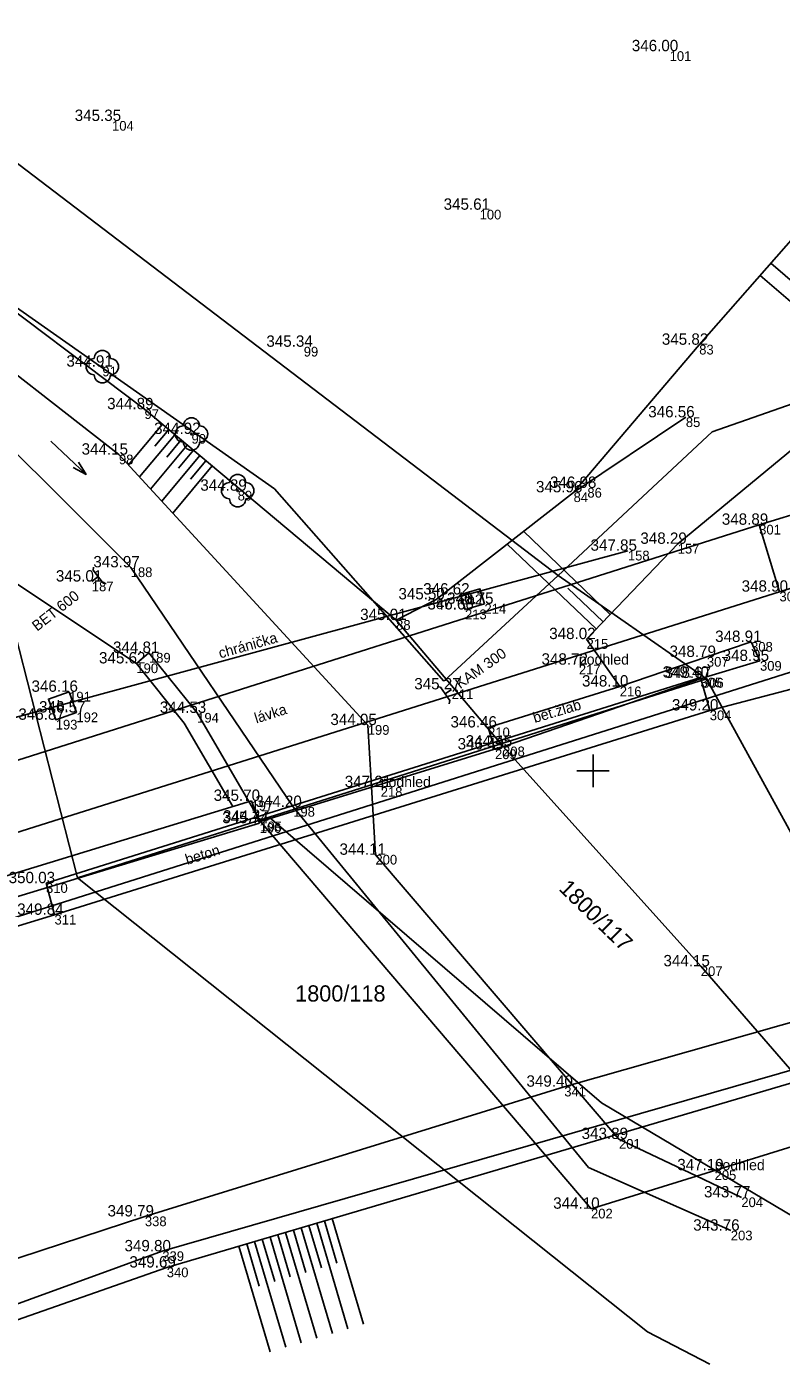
# Model space of a CAD drawing. Extents: x -614046 to -613877, y -1156755 to -1156623.
# Drawn here: x -613953.98 to -613935.35, y -1156734.51 to -1156701.64 of the extents above; entities that cross this region are included whole.
import ezdxf

# ---------------------------------------------------------------- set-up
doc = ezdxf.new("R2010")
doc.units = 0
for name, color, linetype in [('1-bod', 7, 'Continuous'), ('10-silnice', 7, 'Continuous'), ('11-zpevněné plochy', 7, 'Continuous'), ('14-terénní hrany', 7, 'Continuous'), ('15-šrafy', 7, 'Continuous'), ('16-vodní tok', 7, 'Continuous'), ('2-bod výška', 7, 'Continuous'), ('22-stromy', 7, 'Continuous'), ('27-kanalizace značky', 7, 'Continuous'), ('3-bod číslo', 7, 'Continuous'), ('40-popisy povrchů', 7, 'Continuous'), ('45-popis vodní tok', 7, 'Continuous'), ('50-hranice parcel KN', 7, 'Continuous'), ('61-hektarová síť', 7, 'Continuous'), ('7-plot', 7, 'Continuous'), ('9-zábradlí svodidlo', 7, 'Continuous')]:
    doc.layers.add(name, color=color, linetype=linetype)

# ---------------------------------------------------------------- blocks, each defined once
blk = doc.blocks.new('3.13_1')
at = {"layer": '22-stromy'}
blk.add_circle((0, 0), 0.05, dxfattribs=at)
for centre, start, end in [((0, 0.5), 0, 180), ((-0.5, 0), 90, 270), ((0.5, 0), 270, 90), ((0, -0.5), 180, 0)]:
    blk.add_arc(centre, 0.5, start, end, dxfattribs=at)
blk = doc.blocks.new('8.02')
at = {"layer": '45-popis vodní tok'}
blk.add_line((-3, 0), (0, 0), dxfattribs=at)
blk.add_lwpolyline([(-0.876, 0.23), (0, 0), (-0.876, -0.23)], dxfattribs=at)
blk = doc.blocks.new('VT')
at = {"layer": '27-kanalizace značky'}
for p, q in [((-0.629, 0.641), (-0.488, 0.5)), ((-0.488, -0.5), (-0.488, 0.5)), ((-0.488, 0), (0, 0)), ((-0.629, -0.641), (-0.488, -0.5))]:
    blk.add_line(p, q, dxfattribs=at)
blk = doc.blocks.new('POINT_DISPLAY')
blk.add_line((0, 0), (0, 0))

msp = doc.modelspace()

# ---------------------------------------------------------------- linework, layer by layer
at = {"layer": '10-silnice'}
msp.add_line((-613937.12, -1156718.51), (-613953.29, -1156723.55), dxfattribs=at)
for points in [[(-613937.12, -1156718.51), (-613933.57, -1156717.58), (-613925.62, -1156715.79), (-613924.84, -1156714.33), (-613924.32, -1156712.22), (-613924.87, -1156710.22), (-613924.77, -1156707.77), (-613925.4, -1156704.88), (-613927.05, -1156701.37), (-613930.42, -1156695.41), (-613933.78, -1156689.64), (-613939.48, -1156680.87), (-613941.35, -1156679.26), (-613943.8, -1156674.41), (-613943.3, -1156673.71), (-613943.36, -1156673.41), (-613946.37, -1156666.81), (-613948.28, -1156662.1), (-613952.52, -1156653.05)], [(-614040.86, -1156670.12), (-614026.04, -1156676.19), (-614020.49, -1156678.89), (-614017.81, -1156680.62), (-614014.97, -1156682.84), (-614010.02, -1156687.67), (-614005.03, -1156692.4), (-614001.46, -1156696.62), (-613996.56, -1156702.86), (-613991.22, -1156709.86), (-613982.03, -1156721.02), (-613980.56, -1156722.02), (-613978.09, -1156724.42), (-613976.34, -1156726.49), (-613975.01, -1156727.5), (-613973.5, -1156728.21), (-613971.99, -1156728.45), (-613970.47, -1156728.44), (-613968.47, -1156728.24), (-613968.3, -1156728.73), (-613958.25, -1156725.06), (-613953.29, -1156723.55)], [(-613903.37, -1156719.95), (-613913.49, -1156721.34), (-613924.71, -1156723.64), (-613933.07, -1156725.62), (-613940.71, -1156727.79), (-613951.06, -1156730.99), (-613956.76, -1156732.86), (-613974.57, -1156738.23), (-613984.2, -1156741.44), (-613994.97, -1156744.83), (-613999.58, -1156745.99)]]:
    msp.add_lwpolyline(points, dxfattribs=at)
at = {"layer": '11-zpevněné plochy'}
for p, q in [((-613935.9, -1156713.93), (-613926.56, -1156711.05)), ((-613935.4, -1156715.58), (-613925.97, -1156712.68)), ((-613959.11, -1156721.29), (-613935.9, -1156713.93)), ((-613935.9, -1156713.93), (-613935.4, -1156715.58)), ((-613956.51, -1156719.29), (-613939.14, -1156714.57)), ((-613958.54, -1156722.88), (-613935.4, -1156715.58)), ((-613937.19, -1156717.19), (-613936.1, -1156716.82)), ((-613936.1, -1156716.82), (-613935.88, -1156717.29)), ((-613939.34, -1156717.92), (-613937.19, -1156717.19)), ((-613935.88, -1156717.29), (-613937.31, -1156717.71)), ((-613953.5, -1156722.77), (-613937.35, -1156717.7)), ((-613937.31, -1156717.71), (-613942.42, -1156719.47)), ((-613937.35, -1156717.7), (-613937.12, -1156718.51)), ((-613942.59, -1156718.93), (-613939.34, -1156717.92)), ((-613942.42, -1156719.47), (-613942.59, -1156718.93)), ((-613942.22, -1156719.4), (-613948.21, -1156721.25)), ((-613937.34, -1156724.82), (-613942.22, -1156719.4)), ((-613954.8, -1156722.69), (-613948.43, -1156720.74)), ((-613948.43, -1156720.74), (-613948.23, -1156721.29)), ((-613948.23, -1156721.29), (-613954.64, -1156723.23)), ((-613948.21, -1156721.25), (-613940.05, -1156730.8)), ((-613953.29, -1156723.55), (-613953.5, -1156722.77)), ((-613933.83, -1156728.87), (-613937.34, -1156724.82)), ((-613940.05, -1156730.8), (-613933.83, -1156728.87))]:
    msp.add_line(p, q, dxfattribs=at)
for points in [[(-613942.68, -1156715.88), (-613943.16, -1156716.02), (-613943.27, -1156715.65), (-613942.79, -1156715.51)], [(-613952.93, -1156718.05), (-613952.75, -1156718.56), (-613953.26, -1156718.74), (-613953.44, -1156718.23)]]:
    msp.add_lwpolyline(points, close=True, dxfattribs=at)
at = {"layer": '14-terénní hrany'}
for p, q in [((-613959.65, -1156711.78), (-613951.27, -1156717.35)), ((-613940.16, -1156716.75), (-613939.34, -1156717.92))]:
    msp.add_line(p, q, dxfattribs=at)
for points in [[(-613997.04, -1156660.09), (-613993.56, -1156668.05), (-613988.66, -1156677.73), (-613984.98, -1156684.14), (-613979.93, -1156688.52), (-613976.6, -1156692.93), (-613968.24, -1156698.72), (-613963.28, -1156701.99), (-613959.08, -1156705.39), (-613955.46, -1156707.77), (-613951.07, -1156711.08), (-613944.86, -1156716.28)], [(-613940.16, -1156716.75), (-613937.91, -1156714.4), (-613933.94, -1156711.13), (-613930, -1156706.58), (-613928.58, -1156705.01), (-613927.95, -1156702.75), (-613928.18, -1156700.53), (-613933.55, -1156692.05), (-613939.5, -1156686.1), (-613943.86, -1156682.78), (-613948.89, -1156677.3), (-613953.73, -1156674.72)], [(-613951.83, -1156677.12), (-613952.88, -1156678.6), (-613948.44, -1156684.71), (-613942.44, -1156689.03), (-613937.52, -1156693.96), (-613931.49, -1156703.13), (-613933.8, -1156705.42), (-613937.38, -1156709.49), (-613940.48, -1156713.13)], [(-613958.96, -1156738.51), (-613958.16, -1156736.27), (-613957.15, -1156734.85), (-613955.67, -1156734.05), (-613950.52, -1156732.25), (-613932.98, -1156727.07), (-613924.59, -1156724.84)]]:
    msp.add_lwpolyline(points, dxfattribs=at)
at = {"layer": '15-šrafy'}
for p, q in [((-613932.848, -1156709.869), (-613935.61, -1156707.477)), ((-613933.11, -1156710.171), (-613935.874, -1156707.778)), ((-613950.626, -1156711.452), (-613951.466, -1156712.454)), ((-613950.32, -1156711.708), (-613951.193, -1156712.751)), ((-613950.473, -1156711.58), (-613950.816, -1156711.989)), ((-613950.013, -1156711.965), (-613950.92, -1156713.048)), ((-613950.166, -1156711.837), (-613950.522, -1156712.262)), ((-613949.86, -1156712.094), (-613950.229, -1156712.535)), ((-613949.706, -1156712.222), (-613950.646, -1156713.345)), ((-613949.553, -1156712.35), (-613949.936, -1156712.807)), ((-613949.4, -1156712.479), (-613950.373, -1156713.641)), ((-613939.58, -1156716.14), (-613941.72, -1156714.09)), ((-613939.92, -1156716.5), (-613942.12, -1156714.41)), ((-613939.75, -1156716.32), (-613940.62, -1156715.49)), ((-613946.82, -1156731.157), (-613946.05, -1156733.764)), ((-613946.628, -1156731.101), (-613946.32, -1156732.143)), ((-613946.436, -1156731.044), (-613945.666, -1156733.651)), ((-613947.97, -1156731.497), (-613947.201, -1156734.104)), ((-613947.779, -1156731.44), (-613947.471, -1156732.483)), ((-613947.587, -1156731.384), (-613946.817, -1156733.991)), ((-613947.395, -1156731.327), (-613947.087, -1156732.37)), ((-613947.203, -1156731.27), (-613946.433, -1156733.877)), ((-613947.011, -1156731.214), (-613946.703, -1156732.257)), ((-613948.738, -1156731.724), (-613947.968, -1156734.331)), ((-613948.546, -1156731.667), (-613948.238, -1156732.71)), ((-613948.354, -1156731.61), (-613947.584, -1156734.217)), ((-613948.162, -1156731.554), (-613947.854, -1156732.596))]:
    msp.add_line(p, q, dxfattribs=at)
at = {"layer": '16-vodní tok'}
for points in [[(-614001.52, -1156651.1), (-613998.11, -1156660.56), (-613996.01, -1156668.21), (-613990.4, -1156679.18), (-613986.72, -1156685.51), (-613977.75, -1156695.09), (-613969.35, -1156700.93), (-613963.95, -1156705.16), (-613955.95, -1156708.89), (-613951.7, -1156712.2), (-613945.56, -1156718.87), (-613945.478, -1156720.252)], [(-613947.4, -1156720.89), (-613951.41, -1156714.98), (-613956.19, -1156710.22), (-613963.8, -1156706.47), (-613969.59, -1156701.81), (-613978.15, -1156696.55), (-613986.41, -1156688.9), (-613987.27, -1156689.02), (-613988.53, -1156686.84), (-613992.1, -1156680.8), (-613997.89, -1156668.2), (-613999.34, -1156662.5), (-614003.52, -1156652.97)], [(-613945.478, -1156720.252), (-613945.37, -1156722.07), (-613939.36, -1156729.08), (-613937.452, -1156729.99)], [(-613938.735, -1156730.391), (-613940.11, -1156729.78), (-613947.4, -1156720.89)], [(-613937.452, -1156729.99), (-613936.34, -1156730.52)], [(-613936.6, -1156731.34), (-613938.735, -1156730.391)]]:
    msp.add_lwpolyline(points, dxfattribs=at)
at = {"layer": '50-hranice parcel KN'}
for points in [[(-613943.81, -1156712.94), (-613974.5, -1156689.56)], [(-613947.86, -1156713.04), (-613979.96, -1156690.49)], [(-613934.38, -1156710.7), (-613937.06, -1156711.64)], [(-613937.06, -1156711.64), (-613940.86, -1156715.18)], [(-613943.68, -1156717.79), (-613947.86, -1156713.04)], [(-613940.86, -1156715.18), (-613943.81, -1156712.94)], [(-613952.72, -1156722.64), (-613954.79, -1156714.58)], [(-613940.86, -1156715.18), (-613943.68, -1156717.79)], [(-613940.86, -1156715.18), (-613937.2, -1156717.73)], [(-613937.2, -1156717.73), (-613947.99, -1156721.14)], [(-613931.18, -1156728.7), (-613937.2, -1156717.73)], [(-613947.99, -1156721.14), (-613952.72, -1156722.64)], [(-613939.79, -1156728.19), (-613947.99, -1156721.14)], [(-613952.72, -1156722.64), (-613938.66, -1156733.84)], [(-613930.501, -1156733.694), (-613939.79, -1156728.19)], [(-613938.66, -1156733.84), (-613937.118, -1156734.635)]]:
    msp.add_lwpolyline(points, dxfattribs=at)
at = {"layer": '61-hektarová síť'}
for points in [[(-613940, -1156720.4), (-613940, -1156720), (-613940, -1156719.6)], [(-613940.4, -1156720), (-613940, -1156720), (-613939.6, -1156720)]]:
    msp.add_lwpolyline(points, dxfattribs=at)
at = {"layer": '7-plot'}
for p, q in [((-613940.48, -1156713.13), (-613937.71, -1156711.28)), ((-613943.87, -1156715.77), (-613940.48, -1156713.13)), ((-613944.86, -1156716.28), (-613943.87, -1156715.77)), ((-613942.22, -1156719.4), (-613944.86, -1156716.28)), ((-613951.27, -1156717.35), (-613950.09, -1156718.82)), ((-613949.77, -1156718.57), (-613948.21, -1156721.25)), ((-613950.09, -1156718.82), (-613948.89, -1156720.88))]:
    msp.add_line(p, q, dxfattribs=at)
msp.add_lwpolyline([(-613951.27, -1156717.35), (-613950.96, -1156717.09), (-613949.77, -1156718.57)], dxfattribs=at)
at = {"layer": '9-zábradlí svodidlo'}
for points in [[(-613926.75, -1156714.92), (-613959.84, -1156725.38), (-613967.42, -1156727.38), (-613969.94, -1156727.63), (-613973.07, -1156727.23), (-613976.34, -1156725.86), (-613978.17, -1156724.15)], [(-613959.41, -1156738.45), (-613959.23, -1156736.96), (-613958.04, -1156734.97), (-613956.04, -1156733.81), (-613950.63, -1156731.85), (-613933.17, -1156726.82), (-613924.58, -1156724.54), (-613912.88, -1156722.2), (-613903.26, -1156721.01)]]:
    msp.add_lwpolyline(points, dxfattribs=at)

# ---------------------------------------------------------------- block references
at = {"layer": '1-bod'}
for p in [(-613938.11, -1156702.25), (-613951.87, -1156703.97), (-613942.8, -1156706.16), (-613937.38, -1156709.49), (-613947.14, -1156709.54), (-613952.11, -1156710.03), (-613951.07, -1156711.08), (-613937.71, -1156711.28), (-613949.91, -1156711.69), (-613951.7, -1156712.2), (-613948.77, -1156713.09), (-613940.14, -1156713.02), (-613940.48, -1156713.13), (-613935.9, -1156713.93), (-613937.91, -1156714.4), (-613939.14, -1156714.57), (-613951.41, -1156714.98), (-613952.37, -1156715.33), (-613943.27, -1156715.65), (-613935.4, -1156715.58), (-613943.87, -1156715.77), (-613943.16, -1156716.02), (-613942.68, -1156715.88), (-613944.86, -1156716.28), (-613940.16, -1156716.75), (-613936.1, -1156716.82), (-613951.27, -1156717.35), (-613950.96, -1156717.09), (-613940.35, -1156717.38), (-613937.19, -1156717.19), (-613935.88, -1156717.29), (-613937.35, -1156717.7), (-613937.31, -1156717.71), (-613952.93, -1156718.05), (-613943.49, -1156717.99), (-613939.34, -1156717.92), (-613952.75, -1156718.56), (-613949.77, -1156718.57), (-613937.12, -1156718.51), (-613953.26, -1156718.74), (-613945.56, -1156718.87), (-613942.59, -1156718.93), (-613942.42, -1156719.47), (-613942.22, -1156719.4), (-613945.24, -1156720.4), (-613948.43, -1156720.74), (-613947.4, -1156720.89), (-613948.23, -1156721.29), (-613948.21, -1156721.25), (-613945.37, -1156722.07), (-613953.5, -1156722.77), (-613953.29, -1156723.55), (-613937.34, -1156724.82), (-613940.71, -1156727.79), (-613939.36, -1156729.08), (-613937, -1156729.85), (-613936.34, -1156730.52), (-613940.05, -1156730.8), (-613951.06, -1156730.99), (-613936.6, -1156731.34), (-613950.63, -1156731.85), (-613950.52, -1156732.25)]:
    msp.add_blockref('POINT_DISPLAY', p, dxfattribs=at)
at = {"layer": '22-stromy', "xscale": 0.4, "yscale": 0.4000000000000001}
for p in [(-613952.11, -1156710.03), (-613949.91, -1156711.69), (-613948.77, -1156713.09)]:
    msp.add_blockref('3.13_1', p, dxfattribs=at)
at = {"layer": '27-kanalizace značky', "xscale": 0.4}
for p, yscale, rotation in [((-613952.37, -1156715.33), 0.39999999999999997, -141.8641579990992), ((-613943.49, -1156717.99), 0.4000000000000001, 35.24492853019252)]:
    msp.add_blockref('VT', p, dxfattribs=dict(at, yscale=yscale, rotation=rotation))
at = {"layer": '45-popis vodní tok', "xscale": 0.4, "yscale": 0.4000000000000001, "rotation": -43.28164199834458}
msp.add_blockref('8.02', (-613952.51, -1156712.69), dxfattribs=at)

# ---------------------------------------------------------------- texts
at = {"layer": '2-bod výška'}
for s, p in [('346.00 ', (-613939.043, -1156702.25)), ('345.35 ', (-613952.792, -1156703.97)), ('345.61 ', (-613943.687, -1156706.16)), ('345.34 ', (-613948.062, -1156709.54)), ('345.82 ', (-613938.302, -1156709.49)), ('344.91 ', (-613952.997, -1156710.03)), ('344.89 ', (-613951.992, -1156711.08)), ('346.56 ', (-613938.638, -1156711.28)), ('344.92 ', (-613950.832, -1156711.69)), ('344.15 ', (-613952.622, -1156712.2)), ('346.98 ', (-613941.062, -1156713.02)), ('344.89 ', (-613949.692, -1156713.09)), ('345.96 ', (-613941.408, -1156713.13)), ('348.89 ', (-613936.822, -1156713.93)), ('347.85 ', (-613940.062, -1156714.57)), ('348.29 ', (-613938.832, -1156714.4)), ('343.97 ', (-613952.332, -1156714.98)), ('345.01 ', (-613953.257, -1156715.33)), ('346.62 ', (-613944.192, -1156715.65)), ('348.90 ', (-613936.333, -1156715.58)), ('345.50 ', (-613944.803, -1156715.77)), ('346.66 ', (-613944.088, -1156716.02)), ('346.75 ', (-613943.602, -1156715.88)), ('345.01 ', (-613945.747, -1156716.28)), ('348.02 ', (-613941.082, -1156716.75)), ('348.91 ', (-613936.987, -1156716.82)), ('345.62 ', (-613952.192, -1156717.35)), ('344.81 ', (-613951.847, -1156717.09)), ('348.79 ', (-613938.112, -1156717.19)), ('348.95 ', (-613936.802, -1156717.29)), ('348.72 ', (-613941.272, -1156717.38)), ('345.27 ', (-613944.412, -1156717.99)), ('348.10 ', (-613940.273, -1156717.92)), ('349.40 ', (-613938.283, -1156717.7)), ('348.67 ', (-613938.232, -1156717.71)), ('346.16 ', (-613953.858, -1156718.05)), ('346.57 ', (-613953.672, -1156718.56)), ('344.53 ', (-613950.692, -1156718.57)), ('349.20 ', (-613938.053, -1156718.51)), ('346.87 ', (-613954.182, -1156718.74)), ('344.05 ', (-613946.482, -1156718.87)), ('346.46 ', (-613943.518, -1156718.93)), ('346.49 ', (-613943.342, -1156719.47)), ('344.45 ', (-613943.142, -1156719.4)), ('347.21 ', (-613946.127, -1156720.4)), ('345.70 ', (-613949.363, -1156720.74)), ('344.20 ', (-613948.333, -1156720.89)), ('345.74 ', (-613949.152, -1156721.29)), ('344.47 ', (-613949.132, -1156721.25)), ('344.11 ', (-613946.257, -1156722.07)), ('350.03 ', (-613954.422, -1156722.77)), ('349.84 ', (-613954.212, -1156723.55)), ('344.15 ', (-613938.262, -1156724.82)), ('349.40 ', (-613941.643, -1156727.79)), ('343.89 ', (-613940.282, -1156729.08)), ('347.19 ', (-613937.922, -1156729.85)), ('344.10 ', (-613940.983, -1156730.8)), ('343.77 ', (-613937.262, -1156730.52)), ('349.79 ', (-613951.982, -1156730.99)), ('343.76 ', (-613937.528, -1156731.34)), ('349.80 ', (-613951.563, -1156731.85)), ('349.69 ', (-613951.442, -1156732.25))]:
    msp.add_text(s, height=0.28, dxfattribs=at).set_placement(p)
at = {"layer": '3-bod číslo'}
for s, p in [('101', (-613938.11, -1156702.49)), ('104', (-613951.87, -1156704.21)), ('100', (-613942.8, -1156706.4)), ('83', (-613937.38, -1156709.73)), ('99', (-613947.14, -1156709.78)), ('91', (-613952.11, -1156710.27)), ('97', (-613951.07, -1156711.32)), ('85', (-613937.71, -1156711.52)), ('90', (-613949.91, -1156711.93)), ('98', (-613951.7, -1156712.44)), ('89', (-613948.77, -1156713.33)), ('84', (-613940.48, -1156713.37)), ('86', (-613940.14, -1156713.26)), ('301', (-613935.9, -1156714.17)), ('157', (-613937.91, -1156714.64)), ('158', (-613939.14, -1156714.81)), ('188', (-613951.41, -1156715.22)), ('187', (-613952.37, -1156715.57)), ('212', (-613943.27, -1156715.89)), ('302', (-613935.4, -1156715.82)), ('87', (-613943.87, -1156716.01)), ('213', (-613943.16, -1156716.26)), ('214', (-613942.68, -1156716.12)), ('88', (-613944.86, -1156716.52)), ('215', (-613940.16, -1156716.99)), ('308', (-613936.1, -1156717.06)), ('190', (-613951.27, -1156717.59)), ('189', (-613950.96, -1156717.33)), ('217', (-613940.35, -1156717.62)), ('307', (-613937.19, -1156717.43)), ('309', (-613935.88, -1156717.53)), ('305', (-613937.35, -1156717.94)), ('306', (-613937.31, -1156717.95)), ('191', (-613952.93, -1156718.29)), ('211', (-613943.49, -1156718.23)), ('216', (-613939.34, -1156718.16)), ('192', (-613952.75, -1156718.8)), ('194', (-613949.77, -1156718.81)), ('304', (-613937.12, -1156718.75)), ('193', (-613953.26, -1156718.98)), ('199', (-613945.56, -1156719.11)), ('210', (-613942.59, -1156719.17)), ('209', (-613942.42, -1156719.71)), ('208', (-613942.22, -1156719.64)), ('218', (-613945.24, -1156720.64)), ('197', (-613948.43, -1156720.98)), ('198', (-613947.4, -1156721.13)), ('196', (-613948.23, -1156721.53)), ('195', (-613948.21, -1156721.49)), ('200', (-613945.37, -1156722.31)), ('310', (-613953.5, -1156723.01)), ('311', (-613953.29, -1156723.79)), ('207', (-613937.34, -1156725.06)), ('341', (-613940.71, -1156728.03)), ('201', (-613939.36, -1156729.32)), ('205', (-613937, -1156730.09)), ('204', (-613936.34, -1156730.76)), ('202', (-613940.05, -1156731.04)), ('338', (-613951.06, -1156731.23)), ('203', (-613936.6, -1156731.58)), ('339', (-613950.63, -1156732.09)), ('340', (-613950.52, -1156732.49))]:
    msp.add_text(s, height=0.24, dxfattribs=at).set_placement(p)
at = {"layer": '40-popisy povrchů'}
for s, rotation, p in [('BET 600', 38.1358, (-613953.719, -1156716.568)), ('chránička', 15.7275, (-613949.2, -1156717.229)), ('KAM 300', 35.2449, (-613943.281, -1156717.987)), ('bet.žlab', 16.3662, (-613941.44, -1156718.82)), ('lávka', 17.509, (-613948.309, -1156718.833)), ('beton', 17.3116, (-613950.016, -1156722.319))]:
    msp.add_text(s, height=0.26, rotation=rotation, dxfattribs=at).set_placement(p)
for s, p in [('b.', (-613943.113, -1156715.894)), ('podhled', (-613940.35, -1156717.38)), ('b.', (-613953.237, -1156718.522)), ('podhled', (-613945.24, -1156720.4)), ('podhled', (-613937, -1156729.85))]:
    msp.add_text(s, height=0.26, dxfattribs=at).set_placement(p)
at = {"layer": '50-hranice parcel KN'}
msp.add_text('1800/117', height=0.4, rotation=315.9682, dxfattribs=at).set_placement((-613940.867, -1156722.929))
msp.add_text('1800/118', height=0.4, dxfattribs=at).set_placement((-613947.352, -1156725.69))

doc.saveas('drawing.dxf')
